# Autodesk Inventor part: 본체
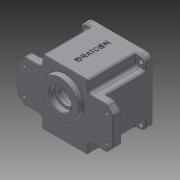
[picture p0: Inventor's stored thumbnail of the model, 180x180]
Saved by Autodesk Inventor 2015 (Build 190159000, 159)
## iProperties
Created: 2016-02
Part Number: 본체
Material: Generic
Document SubType Name: Modeling
Designer: Administrator
Density: 1 g/cm^3
Appearance: Default
Mass: 323.613 g
Surface Area: 761.195 cm^2
Volume: 323.613 cm^3
Author: Administrator
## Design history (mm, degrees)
sketch "Sketch1"
  geometry: L1 (70, 30)-(-70, 30); L2 (-70, 30)-(-70, -30); L3 (-70, -30)-(70, -30); L4 (70, -30)-(70, 30); L5 (70, 30)-(-70, -30); L6 (-70, 30)-(70, -30); 1 further point
  constraints: 12 end point, 2 midpoint, 2 parallel, 1 horizontal, 1 perpendicular
  dimensions: "d0" = 140 distance of L3.end L2.end; "d1" = 60 distance of L2.end L1.end
extrude "Extrusion1" new body sketch "Sketch1" distance "d2" = 12; taper "d3" = 0 deg
sketch "Sketch2"
  geometry: L1 (-33, -47)-(33, -47); L2 (33, -47)-(33, 47); L3 (33, 47)-(-33, 47); L4 (-33, 47)-(-33, -47); L5 (-33, -47)-(33, 47); L6 (33, -47)-(-33, 47); 1 further point
  constraints: 12 end point, 2 midpoint, 2 parallel, 1 horizontal, 1 perpendicular
  dimensions: "d4" = 66 distance of L3.end L2.end; "d5" = 94 distance of L2.end L1.end
extrude "Extrusion2" join sketch "Sketch2" distance "d6" = 79; taper "d7" = 0 deg
sketch "Sketch3"
  geometry: L1 (47, -47)-(-47, -47); L2 (-47, -47)-(-47, 47); L3 (-47, 47)-(47, 47); L4 (47, 47)-(47, -47); L5 (47, -47)-(-47, 47); L6 (-47, -47)-(47, 47); 1 further point
  constraints: 12 end point, 2 midpoint, 2 parallel, 1 horizontal, 1 perpendicular
  dimensions: "d8" = 94 distance of L2.end L3.end; "d9" = 94 distance of L1.end L2.end
extrude "Extrusion3" join sketch "Sketch3" distance "d10" = 10; taper "d11" = 0 deg
sketch "Sketch4"
  geometry: L1 (-47, 30)-(-33, 30); L2 (-33, 30)-(-33, -30); L3 (-33, -30)-(-47, -30); L4 (-47, -30)-(-47, 30); L5 (33, 30)-(47, 30); L6 (47, 30)-(47, -30); L7 (47, -30)-(33, -30); L8 (33, -30)-(33, 30); L9 (-47, 47)-(-47, -47) reference; L10 (47, -47)-(47, 47) reference; 1 further point
  constraints: 16 end point, 4 parallel, 2 collinear, 2 equal length, 2 horizontal, 2 perpendicular
  dimensions: "d12" = 60 distance of L3.end L1.start; "d13" = 30 distance from line of point (0, 0) L1; "d14" = 14 distance of L1.start L1.end; "d15" = 30 distance from line of L5 point (0, 0)
extrude "Extrusion4" join sketch "Sketch4" stored distance "d16" = 10; taper "d17" = 0 deg
chamfer "Chamfer1" distance "d18" = 10; stored, may be unused: second distance "d19" = 2, angle "d20" = 45 deg
sketch "Sketch5"
  geometry: 2 further points
  constraints: 1 coincident
hole "Hole1" sketch "Sketch5" at (0, 0) diameter "d21" = 80; stored, may be unused: countersink angle "d25" = 90 deg, drill point angle "d27" = 0 deg; dims "d22" = 6, "d23" = 86, "d24" = 9, "d26" = 71
sketch "Sketch6"
  geometry: C1 r 21 at (0, -11); C2 r 15 at (0, 20); 1 further point
  constraints: 2 centre point, 2 vertical alignment
  dimensions: "d28" = 11 distance of C1.centre point (0, 0); "d29" = 20 distance of C2.centre point (0, 0); "d30" = 42 diameter of C1; "d31" = 30 diameter of C2
extrude "Extrusion5" join sketch "Sketch6" distance "d32" = 7; taper "d33" = 0 deg
hole "Hole2" diameter "d40" = 25; stored, may be unused: countersink angle "d44" = 90 deg, drill point angle "d46" = 0 deg; dims "d38" = 10, "d39" = 10, "d41" = 6, "d42" = 35, "d43" = 10, "d45" = 15
hole "Hole4" diameter "d58" = 19; stored, may be unused: countersink angle "d62" = 90 deg, drill point angle "d64" = 0 deg; dims "d56" = 10, "d57" = 10, "d59" = 6, "d60" = 22, "d61" = 7, "d63" = 8
sketch "Sketch8"
  geometry: A1 r 36 centre (0, 0) between (-36, 0) and (-35.778, -3.995); A2 r 40 centre (0, 0) between (-39.148, -8.214) and (-39.148, 8.214); A3 r 4 centre (-36, 0) between (-35.852, -3.997) and (-35.852, 3.997); A4 r 3.5 centre (-35.722, -7.495) between (-35.778, -3.995) and (-39.148, -8.214); A5 r 3.5 centre (-35.722, 7.495) between (-39.148, 8.214) and (-35.778, 3.995); A6 r 4 centre (36, 0) between (35.852, 3.997) and (35.852, -3.997); A7 r 3.5 centre (35.722, -7.495) between (39.148, -8.214) and (35.778, -3.995); A8 r 3.5 centre (35.722, 7.495) between (35.778, 3.995) and (39.148, 8.214); 1 further point
  constraints: 26 point on circle, 8 centre point, 8 tangent, 2 coincident, 2 horizontal alignment
  dimensions: "d65" = 36 radius of A1; "d66" = 40 radius of A2; "d67" = 4 radius of A3; "d68" = 3.5 radius of A4; "d69" = 3.5 radius of A5; "d70" = 4 radius of A6; "d71" = 3.5 radius of A7; "d72" = 3.5 radius of A8
extrude "Extrusion7" join sketch "Sketch8" stored distance "d73" = 7; taper "d74" = 0 deg
sketch "Sketch9"
  geometry: L1 (40, 40)-(-40, 40); L2 (-40, 40)-(-40, -40); L3 (-40, -40)-(40, -40); L4 (40, -40)-(40, 40); L5 (40, 40)-(-40, -40); L6 (-40, 40)-(40, -40); 5 further points
  constraints: 12 end point, 4 coincident, 2 midpoint, 2 parallel, 1 horizontal, 1 perpendicular
  dimensions: "d75" = 80 distance of L3.end L2.end; "d76" = 80 distance of L2.end L1.end
hole "Hole5" sketch "Sketch9" at (40, -40), (-40, -40), (-40, 40), (40, 40) diameter "d77" = 7; stored, may be unused: countersink angle "d81" = 90 deg, drill point angle "d83" = 0 deg; dims "d78" = 6, "d79" = 22, "d80" = 7, "d82" = 10
sketch "Sketch10"
  geometry: A1 r 4 centre (36, 0) between (35.852, 3.997) and (35.852, -3.997) reference; A2 r 4 centre (-36, 0) between (-35.852, -3.997) and (-35.852, 3.997) reference; 3 further points
  constraints: 2 coincident
hole "Hole6" sketch "Sketch10" at (36, 0), (-36, 0) diameter "d84" = 3.242; stored, may be unused: countersink angle "d88" = 90 deg, drill point angle "d90" = 118 deg; dims "d85" = 7, "d86" = 22, "d87" = 7, "d89" = 9
sketch "Sketch11"
  geometry: L1 (60, -19)-(-60, -19); L2 (-60, -19)-(-60, 19); L3 (-60, 19)-(60, 19); L4 (60, 19)-(60, -19); L5 (60, -19)-(-60, 19); L6 (-60, -19)-(60, 19); 5 further points
  constraints: 12 end point, 4 coincident, 2 midpoint, 2 parallel, 1 horizontal, 1 perpendicular
  dimensions: "d91" = 120 distance of L2.end L3.end; "d92" = 38 distance of L1.end L2.end
hole "Hole7" sketch "Sketch11" at (60, -19), (60, 19), (-60, 19), (-60, -19) diameter "d93" = 5; stored, may be unused: countersink angle "d97" = 90 deg, drill point angle "d99" = 0 deg; dims "d94" = 7, "d95" = 9, "d96" = 4, "d98" = 9
chamfer "Chamfer2" distance "d100" = 1; stored, may be unused: second distance "d101" = 2, angle "d102" = 45 deg
fillet "Fillet1" dims "d103" = 0.3
fillet "Fillet2" dims "d104" = 3
fillet "Fillet3" dims "d105" = 2
fillet "Fillet5" dims "d139" = 2
fillet "Fillet6" dims "d140" = 8
fillet "Fillet7" dims "d141" = 2
fillet "Fillet8" dims "d142" = 5
fillet "Fillet9" dims "d143" = 2
sketch "Sketch21"
  geometry: L1 (70, -79)-(8, -79) reference; L2 (78, 0)-(0, 0) reference; 3 further points
  constraints: 1 midpoint, 1 vertical alignment, 1 other
  dimensions: "d165" = 40 distance from line of L2 point (39, -40)
emboss "Emboss1" sketch "Sketch21" dims "d8" = 94, "d9" = 94, "d166" = 0.5, "d167" = 0
fillet "Fillet12" dims "d168" = 5
sketch "Sketch23"
  geometry: L1 (-68.536, 21.464)-(-61.464, 28.536) reference; L2 (-70, -17.929)-(-70, 17.929) reference; L3 (-61.464, -28.536)-(-68.536, -21.464) reference; L4 (-38, -30)-(-57.929, -30) reference; L5 (-33, -35)-(-33, -45) reference; L6 (-31, -47)-(31, -47) reference; L7 (33, -45)-(33, -35) reference; L8 (57.929, -30)-(38, -30) reference; L9 (68.536, -21.464)-(61.464, -28.536) reference; L10 (70, 17.929)-(70, -17.929) reference; L11 (61.464, 28.536)-(68.536, 21.464) reference; L12 (38, 30)-(57.929, 30) reference; L13 (33, 35)-(33, 45) reference; L14 (31, 47)-(-31, 47) reference; L15 (-33, 45)-(-33, 35) reference; L16 (-57.929, 30)-(-38, 30) reference; L17 (-31, 46)-(31, 46); L18 (32, 45)-(32, 35); L19 (38, 29)-(57.929, 29); L20 (60.757, 27.828)-(67.828, 20.757); L21 (69, 17.929)-(69, -17.929); L22 (67.828, -20.757)-(60.757, -27.828); L23 (57.929, -29)-(38, -29); L24 (32, -35)-(32, -45); L25 (31, -46)-(-31, -46); L26 (-32, -45)-(-32, -35); L27 (-38, -29)-(-57.929, -29); L28 (-60.757, -27.828)-(-67.828, -20.757); L29 (-69, -17.929)-(-69, 17.929); L30 (-67.828, 20.757)-(-60.757, 27.828); L31 (-57.929, 29)-(-38, 29); L32 (-32, 35)-(-32, 45); C1 r 2.5 at (-60, -19) reference; C2 r 2.5 at (60, 19) reference; C3 r 2.5 at (60, -19) reference; C4 r 2.5 at (-60, 19) reference; C5 r 12.5 at (0, 11) reference; A1 r 5 centre (-57.929, 25) between (-57.929, 30) and (-61.464, 28.536) reference; A2 r 5 centre (-65, 17.929) between (-68.536, 21.464) and (-70, 17.929) reference; A3 r 5 centre (-65, -17.929) between (-70, -17.929) and (-68.536, -21.464) reference; A4 r 5 centre (-57.929, -25) between (-61.464, -28.536) and (-57.929, -30) reference; A5 r 5 centre (-38, -35) between (-33, -35) and (-38, -30) reference; A6 r 2 centre (-31, -45) between (-33, -45) and (-31, -47) reference; A7 r 2 centre (31, -45) between (31, -47) and (33, -45) reference; A8 r 5 centre (38, -35) between (38, -30) and (33, -35) reference; A9 r 5 centre (57.929, -25) between (57.929, -30) and (61.464, -28.536) reference; A10 r 5 centre (65, -17.929) between (68.536, -21.464) and (70, -17.929) reference; A11 r 5 centre (65, 17.929) between (70, 17.929) and (68.536, 21.464) reference; A12 r 5 centre (57.929, 25) between (61.464, 28.536) and (57.929, 30) reference; A13 r 5 centre (38, 35) between (33, 35) and (38, 30) reference; A14 r 2 centre (31, 45) between (33, 45) and (31, 47) reference; A15 r 2 centre (-31, 45) between (-31, 47) and (-33, 45) reference; A16 r 5 centre (-38, 35) between (-38, 30) and (-33, 35) reference; A17 r 1 centre (31, 45) between (32, 45) and (31, 46); A18 r 6 centre (38, 35) between (32, 35) and (38, 29); A19 r 4 centre (57.929, 25) between (60.757, 27.828) and (57.929, 29); A20 r 4 centre (65, 17.929) between (69, 17.929) and (67.828, 20.757); A21 r 4 centre (65, -17.929) between (67.828, -20.757) and (69, -17.929); A22 r 4 centre (57.929, -25) between (57.929, -29) and (60.757, -27.828); A23 r 6 centre (38, -35) between (38, -29) and (32, -35); A24 r 1 centre (31, -45) between (31, -46) and (32, -45); A25 r 1 centre (-31, -45) between (-32, -45) and (-31, -46); A26 r 6 centre (-38, -35) between (-32, -35) and (-38, -29); A27 r 4 centre (-57.929, -25) between (-60.757, -27.828) and (-57.929, -29); A28 r 4 centre (-65, -17.929) between (-69, -17.929) and (-67.828, -20.757); A29 r 4 centre (-65, 17.929) between (-67.828, 20.757) and (-69, 17.929); A30 r 4 centre (-57.929, 25) between (-57.929, 29) and (-60.757, 27.828); A31 r 6 centre (-38, 35) between (-38, 29) and (-32, 35); A32 r 1 centre (-31, 45) between (-31, 46) and (-32, 45); 1 further point
  constraints: 32 end point, 32 point on circle, 16 centre point, 31 other
  dimensions: "d169" = 1 distance between parallel lines of L14 L17
extrude "Extrusion13" join sketch "Sketch23" distance "d170" = 1; taper "d171" = 0 deg
sketch "Sketch24"
  geometry: C1 r 28 at (0, 11); 1 further point
  constraints: 1 centre point, 1 vertical alignment
  dimensions: "d172" = 28 radius of C1; "d173" = 11 distance of point (0, 0) C1.centre
extrude "Extrusion14" join sketch "Sketch24" distance "d174" = 7; taper "d175" = -10 deg
hole "Hole10" diameter "d178" = 32; stored, may be unused: countersink angle "d182" = 90 deg, drill point angle "d184" = 0 deg; dims "d176" = 10, "d177" = 10, "d179" = 7, "d180" = 32, "d181" = 8, "d183" = 8
fillet "Fillet13" dims "d185" = 0.3
chamfer "Chamfer5" distance "d186" = 1; stored, may be unused: second distance "d187" = 2, angle "d188" = 45 deg
fillet "Fillet14" dims "d189" = 0.3
chamfer "Chamfer6" distance "d190" = 1; stored, may be unused: second distance "d191" = 2, angle "d192" = 45 deg
body "Solid1"
node "Projected Loop3"
